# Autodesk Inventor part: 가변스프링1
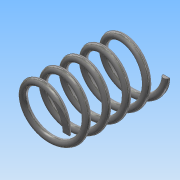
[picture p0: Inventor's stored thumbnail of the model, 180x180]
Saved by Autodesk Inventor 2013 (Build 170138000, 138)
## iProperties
Created: 2018-10
Part Number: 가변스프링1
Material: 스테인리스강
Document SubType Name: Modeling
Designer: Administrator
Density: 8.08 g/cm^3
Mass: 6.29078 g
Surface Area: 15.7849 cm^2
Volume: 0.778561 cm^3
Author: Administrator
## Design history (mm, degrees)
sketch "스케치1"
  geometry: L1 (0, 0)-(0, 30.493); L2 (0, 0)-(8, 0); L3 (0, 30.493)-(8, 30.493); C1 r 1 at (8, 0); 1 further point
  constraints: 6 end point, 2 coincident, 1 centre point, 1 parallel, 1 perpendicular, 1 vertical
  dimensions: "d0" = 30.49299 distance of L1.start L1.end (derived); "d1" = 8 distance of L1.start L2.end; "d2" = 2 diameter of C1; "d3" = 8 distance of L1.end L3.end
feature "코일1" sketch "스케치1" pitch "d4" = 10; turns "d6" = 5; dims "d5" = 30.49299 (= d0), "d7" = 0, angle "d8" = 90 deg, angle "d9" = 90 deg, "d10" = 0, "d11" = 0
sketch "스케치2"
  geometry: L1 (0, -10)-(30.493, -10); L2 (30.493, -10)-(30.493, 10); L3 (30.493, 10)-(0, 10); L4 (0, 10)-(0, -10); 2 further points
  constraints: 8 end point, 2 parallel, 1 coincident, 1 horizontal, 1 midpoint, 1 perpendicular
  dimensions: "d12" = 20 distance of L3.end L1.start; "d14" = 30.49299 distance of L1.start L1.end (derived)
extrude "돌출1" sketch "스케치2" stored distance "d15" = 0; taper "d16" = 0 deg
node "솔리드1"
